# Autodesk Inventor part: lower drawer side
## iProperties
Created: 2005-05
Part Number: lower drawer side
Material: mdf
Document SubType Name: Modeling
Designer: a.campbell
Manufacturer: Standard
Standards Organization: Custom
length: 400
thickness: 12
width: 267
Author: a.campbell
Comments: machine to detail
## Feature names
1. Extrusion1
2. Extrusion2
